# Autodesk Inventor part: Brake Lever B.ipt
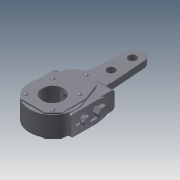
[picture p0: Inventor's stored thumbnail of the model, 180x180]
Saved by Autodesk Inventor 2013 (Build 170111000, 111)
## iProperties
Created: 2005-03
Part Number: Brake Lever B.ipt
Material: Steel, Mild
Document SubType Name: Modeling
Designer: salex
Manufacturer: Standard
Standards Organization: Custom
Density: 7.86 g/cm^3
Mass: 2145.62 g
Surface Area: 686.057 cm^2
Volume: 272.98 cm^3
Author: salex
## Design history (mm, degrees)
derived "B138 02 00 220.iam"
sketch "Эскиз2"
  geometry: L1 (0, 0)-(42.319, 0) reference; L2 (21.319, -88)-(21.319, 62); C1 r 7.5 at (21.319, 62) reference; C2 r 20 at (21.319, -88) reference; C3 r 7.5 at (21.319, 22)
  constraints: 2 end point, 1 centre point, 1 equal radius, 1 perpendicular, 1 point on line
  dimensions: "d0" = 110 distance of C3.centre L2.start
extrude "Выдавливание1" cut sketch "Эскиз2" stored distance "d1" = 10; taper "d2" = 0 deg
body "Solid1"
node "B138 02 00 262 PART1.ipt:1"
node "B138 02 00 222 PART1.ipt:1"
node "B138 02 00 221.ipt:1"
node "B138 02 00 221.ipt:2"
node "zakl_5x20.ipt:1"
node "zakl_5x20.ipt:2"
node "zakl_5x20.ipt:3"
node "zakl_5x20.ipt:4"
node "zakl_5x20.ipt:5"
node "zakl_5x20.ipt:6"
node "zakl_5x20.ipt:7"
node "zakl_5x20.ipt:8"
node "zakl_5x20.ipt:9"
node "zakl_5x20.ipt:10"
node "S_8.ipt:1"
node "Bolt_M8x16.iam:1::Bolt_M8x16 PART1.ipt:1"
node "B138 02 00 223.ipt:1"
